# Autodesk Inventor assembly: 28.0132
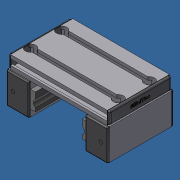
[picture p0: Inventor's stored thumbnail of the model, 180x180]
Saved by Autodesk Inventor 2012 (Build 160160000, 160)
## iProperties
Created: 2007-06
Part Number: 28.0132
Document SubType Name: Assembly
Designer: Andy Moles
Description: SLIDE LWG 32X45-45
FINISH: N/A
Author: Andy Moles
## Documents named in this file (8)
- C:\Andys Backup Data\ANDY'S INVENTOR\INVENTOR LIBRARIES\PARTS LIBRARY\READY FOR USE MODULES LG\28.0132 SLIDE LWG 32X45-45.iam
- C:\Andys Backup Data\ANDY'S INVENTOR\INVENTOR LIBRARIES\PARTS LIBRARY\READY FOR USE MODULES LG\SUBCOMPONENTS\28.0126 SLIDE 45X32.ipt
- C:\Andys Backup Data\ANDY'S INVENTOR\INVENTOR LIBRARIES\PARTS LIBRARY\COMPONENTS LG\22.1094 SLIDE RAIL LG.iam
- C:\Andys Backup Data\ANDY'S INVENTOR\INVENTOR LIBRARIES\PARTS LIBRARY\READY FOR USE MODULES LG\SUBCOMPONENTS\28.0223 SLIDE LWG 32X45-45 90X19.ipt
- C:\Andys Backup Data\ANDY'S INVENTOR\INVENTOR LIBRARIES\PARTS LIBRARY\FASTENING ELEMENTS\SCREWS CAP\21.1200 M8X16.ipt
- C:\Andys Backup Data\ANDY'S INVENTOR\INVENTOR LIBRARIES\PARTS LIBRARY\FASTENING ELEMENTS\NUTS\21.1351 M8 SQUARE NUT.ipt
- C:\Andys Backup Data\ANDY'S INVENTOR\INVENTOR LIBRARIES\PARTS LIBRARY\END CAPS\22.1014_1 END CAP 90X19 GRAY.ipt
- C:\Andys Backup Data\ANDY'S INVENTOR\INVENTOR LIBRARIES\PARTS LIBRARY\END CAPS\22.1003_1 END CAP 45x32 Z Gray.iam
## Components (19 placed, 7 different names)
1. 28.0223 SLIDE LWG 32X45-45 90X19:1 — Mate:8, Flush:5, Flush:6, Insert:1, Insert:2, Insert:3, Insert:4, Mate:15, Flush:19, Mate:17, Insert:5, Insert:6, Insert:7, Insert:8, Mate:18, Flush:20, Flush:21, Mate:19, Flush:22, Flush:23
2. 28.0126 SLIDE 45X32:1 — Mate:1, Flush:1, Flush:2, Flush:3, Mate:7, Mate:8, Flush:5, Flush:6, Mate:16, Mate:21, Flush:26, Flush:27, Mate:22, Flush:28, Flush:29
3. 28.0126 SLIDE 45X32:2 — Flush:2, Flush:3, Mate:3, Flush:4, Mate:6, Mate:7, Mate:20, Flush:24, Flush:25, Mate:23, Flush:30, Flush:31
4. 22.1094 SLIDE RAIL LG:1 [sub-assembly] — Mate:1, Flush:1, Mate:16
5. 22.1094 SLIDE RAIL LG:2 [sub-assembly] — Mate:3, Flush:4, Mate:6
6. 22.1014_1 END CAP 90X19 GRAY:1 — Mate:19, Flush:22, Flush:23
7. 22.1014_1 END CAP 90X19 GRAY:2 — Mate:18, Flush:20, Flush:21
8. 21.1200 M8 x 16:1 — Insert:2
9. 21.1200 M8 x 16:2 — Insert:1
10. 21.1200 M8 x 16:3 — Insert:3
11. 21.1200 M8 x 16:4 — Insert:4
12. 21.1351 M8 SQUARE NUT:1 — Insert:5
13. 21.1351 M8 SQUARE NUT:2 — Insert:6
14. 21.1351 M8 SQUARE NUT:3 — Insert:7
15. 21.1351 M8 SQUARE NUT:4 — Insert:8
16. 22.1003_1 END CAP 45x32 Z Gray:1 [sub-assembly] — Mate:20, Flush:24, Flush:25
17. 22.1003_1 END CAP 45x32 Z Gray:2 [sub-assembly] — Mate:23, Flush:30, Flush:31
18. 22.1003_1 END CAP 45x32 Z Gray:3 [sub-assembly] — Mate:22, Flush:28, Flush:29
19. 22.1003_1 END CAP 45x32 Z Gray:4 [sub-assembly] — Mate:21, Flush:26, Flush:27
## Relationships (41: Flush 19, Mate 14, Insert 8)
- Mate:1: 28.0126 SLIDE 45X32:1 ↔ 22.1094 SLIDE RAIL LG:1
- Flush:1: 28.0126 SLIDE 45X32:1 ↔ 22.1094 SLIDE RAIL LG:1
- Flush:2: 28.0126 SLIDE 45X32:1 ↔ 28.0126 SLIDE 45X32:2
- Flush:3: 28.0126 SLIDE 45X32:1 ↔ 28.0126 SLIDE 45X32:2
- Mate:3: 28.0126 SLIDE 45X32:2 ↔ 22.1094 SLIDE RAIL LG:2
- Flush:4: 28.0126 SLIDE 45X32:2 ↔ 22.1094 SLIDE RAIL LG:2
- Mate:6: 28.0126 SLIDE 45X32:2 ↔ 22.1094 SLIDE RAIL LG:2
- Mate:7: 28.0126 SLIDE 45X32:1 ↔ 28.0126 SLIDE 45X32:2
- Mate:8: 28.0223 SLIDE LWG 32X45-45 90X19:1 ↔ 28.0126 SLIDE 45X32:1
- Flush:5: 28.0223 SLIDE LWG 32X45-45 90X19:1 ↔ 28.0126 SLIDE 45X32:1
- Flush:6: 28.0223 SLIDE LWG 32X45-45 90X19:1 ↔ 28.0126 SLIDE 45X32:1
- Insert:1: 28.0223 SLIDE LWG 32X45-45 90X19:1 ↔ 21.1200 M8 x 16:2
- Insert:2: 28.0223 SLIDE LWG 32X45-45 90X19:1 ↔ 21.1200 M8 x 16:1
- Insert:3: 28.0223 SLIDE LWG 32X45-45 90X19:1 ↔ 21.1200 M8 x 16:3
- Insert:4: 28.0223 SLIDE LWG 32X45-45 90X19:1 ↔ 21.1200 M8 x 16:4
- Mate:15: 28.0223 SLIDE LWG 32X45-45 90X19:1
- Flush:19: 28.0223 SLIDE LWG 32X45-45 90X19:1
- Mate:16: 28.0126 SLIDE 45X32:1 ↔ 22.1094 SLIDE RAIL LG:1
- Mate:17: 28.0223 SLIDE LWG 32X45-45 90X19:1
- Insert:5: 28.0223 SLIDE LWG 32X45-45 90X19:1 ↔ 21.1351 M8 SQUARE NUT:1
- Insert:6: 28.0223 SLIDE LWG 32X45-45 90X19:1 ↔ 21.1351 M8 SQUARE NUT:2
- Insert:7: 28.0223 SLIDE LWG 32X45-45 90X19:1 ↔ 21.1351 M8 SQUARE NUT:3
- Insert:8: 28.0223 SLIDE LWG 32X45-45 90X19:1 ↔ 21.1351 M8 SQUARE NUT:4
- Mate:18: 28.0223 SLIDE LWG 32X45-45 90X19:1 ↔ 22.1014_1 END CAP 90X19 GRAY:2
- Flush:20: 28.0223 SLIDE LWG 32X45-45 90X19:1 ↔ 22.1014_1 END CAP 90X19 GRAY:2
- Flush:21: 28.0223 SLIDE LWG 32X45-45 90X19:1 ↔ 22.1014_1 END CAP 90X19 GRAY:2
- Mate:19: 28.0223 SLIDE LWG 32X45-45 90X19:1 ↔ 22.1014_1 END CAP 90X19 GRAY:1
- Flush:22: 28.0223 SLIDE LWG 32X45-45 90X19:1 ↔ 22.1014_1 END CAP 90X19 GRAY:1
- Flush:23: 28.0223 SLIDE LWG 32X45-45 90X19:1 ↔ 22.1014_1 END CAP 90X19 GRAY:1
- Mate:20: 28.0126 SLIDE 45X32:2 ↔ 22.1003_1 END CAP 45x32 Z Gray:1
- Flush:24: 28.0126 SLIDE 45X32:2 ↔ 22.1003_1 END CAP 45x32 Z Gray:1
- Flush:25: 28.0126 SLIDE 45X32:2 ↔ 22.1003_1 END CAP 45x32 Z Gray:1
- Mate:21: 28.0126 SLIDE 45X32:1 ↔ 22.1003_1 END CAP 45x32 Z Gray:4
- Flush:26: 28.0126 SLIDE 45X32:1 ↔ 22.1003_1 END CAP 45x32 Z Gray:4
- Flush:27: 28.0126 SLIDE 45X32:1 ↔ 22.1003_1 END CAP 45x32 Z Gray:4
- Mate:22: 28.0126 SLIDE 45X32:1 ↔ 22.1003_1 END CAP 45x32 Z Gray:3
- Flush:28: 28.0126 SLIDE 45X32:1 ↔ 22.1003_1 END CAP 45x32 Z Gray:3
- Flush:29: 28.0126 SLIDE 45X32:1 ↔ 22.1003_1 END CAP 45x32 Z Gray:3
- Mate:23: 28.0126 SLIDE 45X32:2 ↔ 22.1003_1 END CAP 45x32 Z Gray:2
- Flush:30: 28.0126 SLIDE 45X32:2 ↔ 22.1003_1 END CAP 45x32 Z Gray:2
- Flush:31: 28.0126 SLIDE 45X32:2 ↔ 22.1003_1 END CAP 45x32 Z Gray:2
